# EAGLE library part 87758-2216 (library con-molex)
22 Pin - 2mm Dual Row Single Wafer, Vertical T/H HDR Source: http://www.molex.com/pdm_docs/sd/877580616_sd.pdf
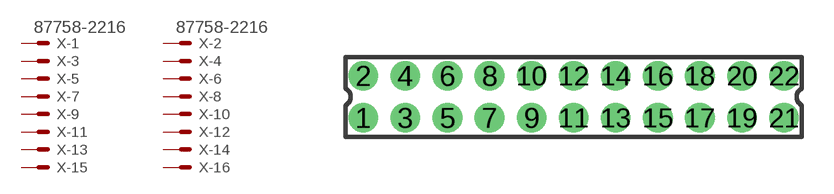
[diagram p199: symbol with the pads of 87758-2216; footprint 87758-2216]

Designator prefix X; gates -1=MV -2=MV -3=M -4=M -5=M -6=M -7=M -8=M -9=M -10=M -11=M -12=M -13=M -14=M -15=M -16=M -17=M -18=M -19=M -20=M -21=M -22=M

## 87758-2216 (MPN: 87758-2216; OC_FARNELL: unknown; OC_NEWARK: 94M1536)  [87758-2216]
1  -1:S  pas
2  -2:S  pas
3  -3:S  pas
4  -4:S  pas
5  -5:S  pas
6  -6:S  pas
7  -7:S  pas
8  -8:S  pas
9  -9:S  pas
10  -10:S  pas
11  -11:S  pas
12  -12:S  pas
13  -13:S  pas
14  -14:S  pas
15  -15:S  pas
16  -16:S  pas
17  -17:S  pas
18  -18:S  pas
19  -19:S  pas
20  -20:S  pas
21  -21:S  pas
22  -22:S  pas

## Footprint 87758-2216 (pad centres in mm)
22 Pin - 2mm Dual Row Single Wafer, Vertical T/H HDR Source: http://www.molex.com/pdm_docs/sd/877580616_sd.pdf
drill 0.9 pad 1.27 round: 1 -10,-1; 2 -10,1; 3 -8,-1; 4 -8,1; 5 -6,-1; 6 -6,1; 7 -4,-1; 8 -4,1; 9 -2,-1; 10 -2,1; 11 0,-1; 12 0,1; 13 2,-1; 14 2,1; 15 4,-1; 16 4,1; 17 6,-1; 18 6,1; 19 8,-1; 20 8,1; 21 10,-1; 22 10,1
